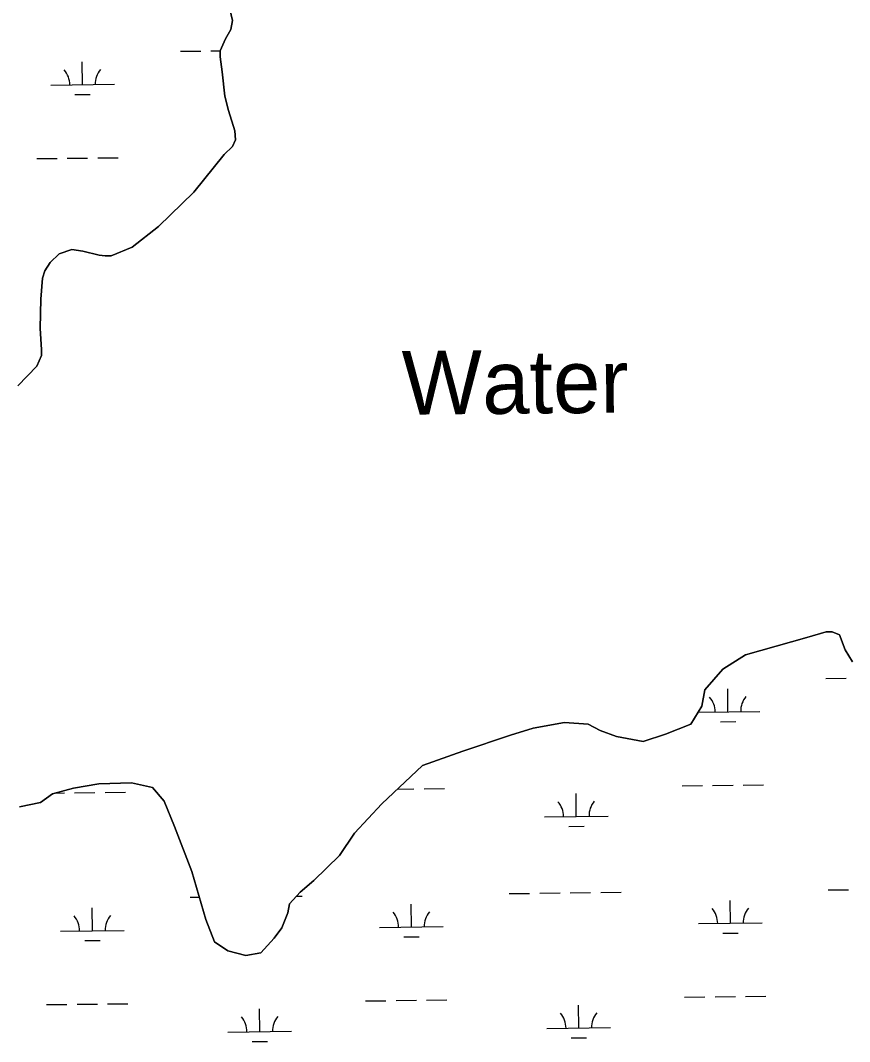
# Model space of a CAD drawing. Extents: x 3684037 to 3722149, y 433263 to 459021.
# Drawn here: x 3702168 to 3703473, y 440497 to 442103 of the extents above; entities that cross this region are included whole.
import ezdxf

# ---------------------------------------------------------------- set-up
doc = ezdxf.new("R2010")
doc.units = 0
for name, color, linetype in [('V-RIVR-IDEN', 7, 'Continuous'), ('V-TOPO-SHOR', 7, 'Continuous'), ('V-WETL-SWMP', 7, 'Continuous')]:
    doc.layers.add(name, color=color, linetype=linetype)

msp = doc.modelspace()

# ---------------------------------------------------------------- linework, layer by layer
at = {"layer": 'V-TOPO-SHOR'}
for points in [[(3702496.2, 442128.1), (3702501.7, 442103.4), (3702499.2, 442089.4), (3702490.8, 442074.3), (3702482.4, 442055.6), (3702482.3, 442046.3), (3702485.5, 442022.8), (3702489.7, 441984.1), (3702495.3, 441961.7), (3702505.5, 441930), (3702506.5, 441915.9), (3702501.7, 441905.4), (3702488.6, 441892.7), (3702441, 441833.5), (3702385.3, 441779.1), (3702343.9, 441746.8), (3702310.9, 441733.1), (3702301.6, 441733.2), (3702292.2, 441734.5), (3702266.5, 441740.7), (3702249, 441743.2), (3702229, 441736.4), (3702214.7, 441722.5), (3702206.4, 441709.8), (3702202.7, 441698.1), (3702200, 441665.3), (3702199.4, 441619.6), (3702201.4, 441585.6), (3702201.2, 441576.2), (3702194, 441559.9), (3702164.3, 441528.6)], [(3702166.9, 440866.5), (3702199.8, 440873.2), (3702218.7, 440887), (3702251.6, 440896), (3702291.6, 440902.5), (3702343.1, 440904.2), (3702375.9, 440896.8), (3702394.4, 440875.5), (3702410.3, 440835.5), (3702437.6, 440764.8), (3702460.1, 440689.6), (3702473.7, 440654.2), (3702494.6, 440639.9), (3702522.7, 440632.6), (3702546.2, 440637), (3702567.5, 440660.2), (3702579.4, 440676.4), (3702589.1, 440699.7), (3702591.6, 440713.8), (3702608.2, 440732.3), (3702629.6, 440750.8), (3702669.9, 440790.2), (3702693.7, 440825), (3702736.5, 440871.4), (3702800.5, 440931.6), (3702864, 440954.2), (3702939.3, 440979.1), (3702974.6, 440990.4), (3703023.9, 440999.2), (3703061.4, 440996.4), (3703080, 440986.8), (3703105.7, 440977.1), (3703147.8, 440969.6), (3703183.1, 440980.8), (3703223.1, 440996.8), (3703239.9, 441024.7), (3703244.9, 441050.4), (3703273.4, 441082.9), (3703308.8, 441105.9), (3703405.2, 441132.9), (3703435.8, 441141.9), (3703445.2, 441141.7), (3703456.8, 441136.9), (3703465.9, 441113.4), (3703477.4, 441094.5)]]:
    msp.add_lwpolyline(points, dxfattribs=at)
at = {"layer": 'V-WETL-SWMP'}
for p, q in [((3702419.9, 442054.9), (3702451.9, 442055.3)), ((3702467.9, 442055.5), (3702482.4, 442055.6)), ((3702265.9, 442002.4), (3702265.5, 442038.4)), ((3702215.9, 442001.8), (3702315.9, 442003)), ((3702254, 441986.8), (3702278, 441987.1)), ((3702193.8, 441886.1), (3702225.8, 441886.5)), ((3702241.8, 441886.6), (3702273.8, 441887)), ((3702289.8, 441887.2), (3702321.8, 441887.6)), ((3703435.2, 441068.6), (3703467.2, 441069)), ((3703281.2, 441016.1), (3703280.8, 441052.1)), ((3703234.4, 441015.5), (3703331.2, 441016.7)), ((3703269.4, 441000.5), (3703293.4, 441000.8)), ((3703257.2, 440900.4), (3703289.2, 440900.7)), ((3703305.2, 440900.9), (3703337.2, 440901.3)), ((3702223.7, 440888.3), (3702237.4, 440888.5)), ((3702253.4, 440888.7), (3702285.4, 440889.1)), ((3702301.4, 440889.3), (3702333.4, 440889.6)), ((3702761.2, 440894.6), (3702787.3, 440894.9)), ((3702803.3, 440895.1), (3702835.3, 440895.5)), ((3703042.7, 440851.4), (3703042.2, 440887.4)), ((3703209.2, 440899.8), (3703241.2, 440900.2)), ((3702992.7, 440850.9), (3703092.7, 440852)), ((3703030.8, 440835.9), (3703054.8, 440836.2)), ((3702435.3, 440724.3), (3702449.6, 440724.5)), ((3702602.8, 440726.2), (3702611.3, 440726.3)), ((3702937.2, 440730.1), (3702969.2, 440730.5)), ((3702985.2, 440730.7), (3703017.2, 440731.1)), ((3703033.2, 440731.3), (3703065.2, 440731.6)), ((3703081.2, 440731.8), (3703113.2, 440732.2)), ((3703439.1, 440736), (3703471.1, 440736.3)), ((3702783.2, 440677.6), (3702782.8, 440713.6)), ((3703285.1, 440683.4), (3703284.7, 440719.4)), ((3702281.4, 440671.8), (3702280.9, 440707.8)), ((3702733.2, 440677), (3702833.2, 440678.2)), ((3703235.1, 440682.9), (3703335.1, 440684)), ((3702231.4, 440671.2), (3702331.3, 440672.3)), ((3702771.4, 440662), (3702795.4, 440662.3)), ((3703273.3, 440667.9), (3703297.3, 440668.1)), ((3702269.5, 440656.2), (3702293.5, 440656.5)), ((3703213, 440567.2), (3703245, 440567.5)), ((3703261, 440567.7), (3703293, 440568.1)), ((3703309, 440568.3), (3703341, 440568.7)), ((3702209.3, 440555.5), (3702241.3, 440555.9)), ((3702257.3, 440556), (3702289.3, 440556.4)), ((3702305.3, 440556.6), (3702337.3, 440557)), ((3702544.7, 440513), (3702544.2, 440548.9)), ((3702711.2, 440561.3), (3702743.2, 440561.7)), ((3702759.2, 440561.9), (3702791.2, 440562.3)), ((3702807.2, 440562.4), (3702839.2, 440562.8)), ((3703046.5, 440518.8), (3703046.1, 440554.8)), ((3702996.5, 440518.2), (3703096.5, 440519.4)), ((3702494.7, 440512.4), (3702594.7, 440513.5)), ((3703034.7, 440503.2), (3703058.7, 440503.5)), ((3702532.8, 440497.4), (3702556.8, 440497.7))]:
    msp.add_line(p, q, dxfattribs=at)
for points in [[(3702164.3, 441528.6), (3702194, 441559.9), (3702201.2, 441576.2), (3702201.4, 441585.6), (3702199.4, 441619.6), (3702200, 441665.3), (3702202.7, 441698.1), (3702206.4, 441709.8), (3702214.7, 441722.5), (3702229, 441736.4), (3702249, 441743.2), (3702266.5, 441740.7), (3702292.2, 441734.5), (3702301.6, 441733.2), (3702310.9, 441733.1), (3702343.9, 441746.8), (3702385.3, 441779.1), (3702441, 441833.5), (3702488.6, 441892.7), (3702501.7, 441905.4), (3702506.5, 441915.9), (3702505.5, 441930), (3702495.3, 441961.7), (3702489.7, 441984.1), (3702485.5, 442022.8), (3702482.3, 442046.3), (3702482.4, 442055.6), (3702490.8, 442074.3), (3702499.2, 442089.4), (3702501.7, 442103.4), (3702496.2, 442128.1)], [(3703477.4, 441094.5), (3703465.9, 441113.4), (3703456.8, 441136.9), (3703445.2, 441141.7), (3703435.8, 441141.9), (3703405.2, 441132.9), (3703308.8, 441105.9), (3703273.4, 441082.9), (3703244.9, 441050.4), (3703239.9, 441024.7), (3703223.1, 440996.8), (3703183.1, 440980.8), (3703147.8, 440969.6), (3703105.7, 440977.1), (3703080, 440986.8), (3703061.4, 440996.4), (3703023.9, 440999.2), (3702974.6, 440990.4), (3702939.3, 440979.1), (3702864, 440954.2), (3702800.5, 440931.6), (3702736.5, 440871.4), (3702693.7, 440825), (3702669.9, 440790.2), (3702629.6, 440750.8), (3702608.2, 440732.3), (3702591.6, 440713.8), (3702589.1, 440699.7), (3702579.4, 440676.4), (3702567.5, 440660.2), (3702546.2, 440637), (3702522.7, 440632.6), (3702494.6, 440639.9), (3702473.7, 440654.2), (3702460.1, 440689.6), (3702437.6, 440764.8), (3702410.3, 440835.5), (3702394.4, 440875.5), (3702375.9, 440896.8), (3702343.1, 440904.2), (3702291.6, 440902.5), (3702251.6, 440896), (3702218.7, 440887), (3702199.8, 440873.2), (3702166.9, 440866.5)]]:
    msp.add_lwpolyline(points, dxfattribs=at)
for centre, start, end in [((3702210.6, 442002.2), 359.8949, 41.4385), ((3702321.1, 442003.5), 139.8949, 181.4385), ((3703226, 441015.9), 359.8949, 41.4385), ((3703336.5, 441017.2), 139.8949, 181.4385), ((3702987.4, 440851.3), 359.8949, 41.4385), ((3703097.9, 440852.6), 139.8949, 181.4385), ((3702226.1, 440671.6), 359.8949, 41.4385), ((3702336.6, 440672.9), 139.8949, 181.4385), ((3702728, 440677.4), 359.8949, 41.4385), ((3702838.5, 440678.7), 139.8949, 181.4385), ((3703229.9, 440683.3), 359.8949, 41.4385), ((3703340.3, 440684.6), 139.8949, 181.4385), ((3702489.4, 440512.8), 359.8949, 41.4385), ((3702599.9, 440514.1), 139.8949, 181.4385), ((3702991.3, 440518.6), 359.8949, 41.4385), ((3703101.8, 440519.9), 139.8949, 181.4385)]:
    msp.add_arc(centre, 35.2, start, end, dxfattribs=at)

# ---------------------------------------------------------------- texts
at = {"layer": 'V-RIVR-IDEN'}
msp.add_text('Water', height=100, rotation=0.5305, dxfattribs=at).set_placement((3702768.7, 441483.3))

doc.saveas('drawing.dxf')
